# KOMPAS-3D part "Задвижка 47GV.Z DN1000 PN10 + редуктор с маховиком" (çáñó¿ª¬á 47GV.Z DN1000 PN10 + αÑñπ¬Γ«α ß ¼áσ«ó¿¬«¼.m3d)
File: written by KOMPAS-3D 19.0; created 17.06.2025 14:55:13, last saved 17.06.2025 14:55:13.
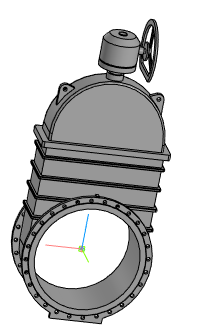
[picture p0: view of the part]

Document properties: Полное имя файла: Задвижка 47GV.Z DN1000 PN10 + редуктор с маховиком.a3d

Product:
- Part/product: Задвижка 47GV.Z DN1000 PN10 + редуктор с маховиком
    Масса: 4516.05

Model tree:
1. Операция без истории:1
